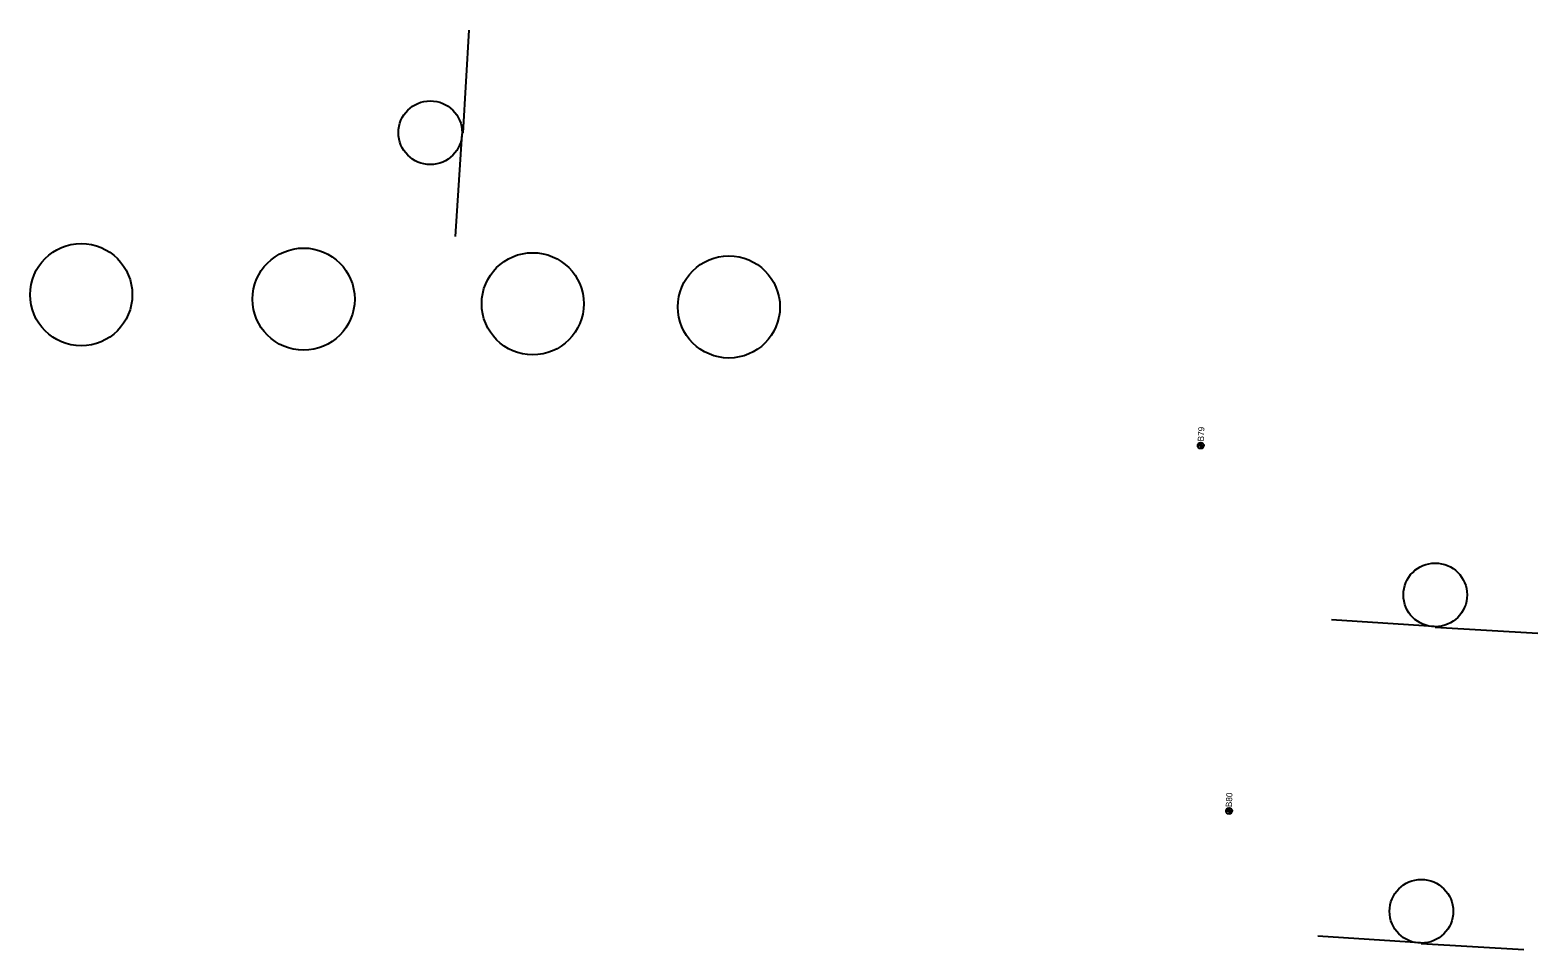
# Model space of a CAD drawing. Extents: x 327762 to 372792, y 127949 to 259367.
# Drawn here: x 358164 to 360635, y 173908 to 175415 of the extents above; entities that cross this region are included whole.
import ezdxf

# ---------------------------------------------------------------- set-up
doc = ezdxf.new("R2010")
doc.units = 0
for name, color, linetype in [('CE-TOPO-CONC-SLAB', 7, 'Continuous'), ('E_SOIL_BORE1 [KAPUR_CADDS_LEVELS]', 7, 'Continuous'), ('E_SOIL_BORE2 [KAPUR_CADDS_LEVELS]', 7, 'Continuous'), ('P_MARK', 7, 'Continuous'), ('SIGNS-POLES', 7, 'Continuous')]:
    doc.layers.add(name, color=color, linetype=linetype)

msp = doc.modelspace()

# ---------------------------------------------------------------- linework, layer by layer
at = {"layer": 'CE-TOPO-CONC-SLAB'}
for centre in [(358248, 174982), (358612.4, 174974.7), (358987.9, 174967.1), (359309.3, 174961.9)]:
    msp.add_circle(centre, 83.7, dxfattribs=at)
at = {"layer": 'P_MARK'}
for p, q in [((360077.6, 174734.7), (360087.6, 174734.7)), ((360082.6, 174739.7), (360082.6, 174729.7)), ((360124, 174136), (360134, 174136)), ((360129, 174141), (360129, 174131))]:
    msp.add_line(p, q, dxfattribs=at)
for centre in [(360082.6, 174734.7), (360129, 174136)]:
    msp.add_circle(centre, 5, dxfattribs=at)
for centre, radius, start, end in [((360082.6, 174734.7), 4.5, 89.9869, 179.9869), ((360082.6, 174734.7), 4, 89.9869, 179.9869), ((360082.6, 174734.7), 3.5, 89.9869, 179.9869), ((360082.6, 174734.7), 3, 89.9869, 179.9869), ((360082.6, 174734.7), 2.5, 89.9869, 179.9869), ((360082.6, 174734.7), 2, 89.9869, 179.9869), ((360082.6, 174734.7), 1.5, 89.9869, 179.9869), ((360082.6, 174734.7), 1, 89.9869, 179.9869), ((360082.6, 174734.7), 0.5, 89.9869, 179.9869), ((360082.6, 174734.7), 4.5, 269.9869, 359.9869), ((360082.6, 174734.7), 4, 269.9869, 359.9869), ((360082.6, 174734.7), 3.5, 269.9869, 359.9869), ((360082.6, 174734.7), 3, 269.9869, 359.9869), ((360082.6, 174734.7), 2.5, 269.9869, 359.9869), ((360082.6, 174734.7), 2, 269.9869, 359.9869), ((360082.6, 174734.7), 1.5, 269.9869, 359.9869), ((360082.6, 174734.7), 1, 269.9869, 359.9869), ((360082.6, 174734.7), 0.5, 269.9869, 359.9869), ((360129, 174136), 4.5, 89.9869, 179.9869), ((360129, 174136), 4, 89.9869, 179.9869), ((360129, 174136), 3.5, 89.9869, 179.9869), ((360129, 174136), 3, 89.9869, 179.9869), ((360129, 174136), 2.5, 89.9869, 179.9869), ((360129, 174136), 2, 89.9869, 179.9869), ((360129, 174136), 1.5, 89.9869, 179.9869), ((360129, 174136), 1, 89.9869, 179.9869), ((360129, 174136), 0.5, 89.9869, 179.9869), ((360129, 174136), 4.5, 269.9869, 359.9869), ((360129, 174136), 4, 269.9869, 359.9869), ((360129, 174136), 3.5, 269.9869, 359.9869), ((360129, 174136), 3, 269.9869, 359.9869), ((360129, 174136), 2.5, 269.9869, 359.9869), ((360129, 174136), 2, 269.9869, 359.9869), ((360129, 174136), 1.5, 269.9869, 359.9869), ((360129, 174136), 1, 269.9869, 359.9869), ((360129, 174136), 0.5, 269.9869, 359.9869)]:
    msp.add_arc(centre, radius, start, end, dxfattribs=at)
at = {"layer": 'SIGNS-POLES'}
for p, q in [((358883.2, 175415.5), (358873.3, 175247)), ((358871.9, 175245.8), (358860.7, 175077.5)), ((360465.3, 174438.1), (360296.9, 174449.3)), ((360634.9, 174426.8), (360466.5, 174436.7)), ((360442.6, 173919.7), (360274.2, 173930.9)), ((360612.2, 173908.3), (360443.7, 173918.3))]:
    msp.add_line(p, q, dxfattribs=at)
for centre in [(358820, 175247.4), (360466.8, 174490), (360444.1, 173971.5)]:
    msp.add_circle(centre, 52.2, dxfattribs=at)

# ---------------------------------------------------------------- texts
at = {"layer": 'E_SOIL_BORE1 [KAPUR_CADDS_LEVELS]'}
msp.add_text('B80', height=10, rotation=87.2646, dxfattribs=at).set_placement((360133.4, 174142.1))
at = {"layer": 'E_SOIL_BORE2 [KAPUR_CADDS_LEVELS]'}
msp.add_text('B79', height=10, rotation=87.2646, dxfattribs=at).set_placement((360087.5, 174741.4))

doc.saveas('drawing.dxf')
